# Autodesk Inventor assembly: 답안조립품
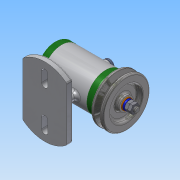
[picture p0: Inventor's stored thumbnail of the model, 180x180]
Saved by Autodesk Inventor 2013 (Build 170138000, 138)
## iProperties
Created: 2017-12
Part Number: 답안조립품
Document SubType Name: Assembly
Designer: Administrator
Author: Administrator
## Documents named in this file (14)
- C:\Users\Administrator\Desktop\471208V1024\답안조립품.iam
- C:\Users\Administrator\Desktop\471208V1024\V벨트풀리.ipt
- C:\Users\Administrator\Desktop\471208V1024\고무캡.ipt
- C:\Users\Administrator\Desktop\471208V1024\너트 M 8.ipt
- C:\Users\Administrator\Desktop\471208V1024\뒤커버.ipt
- C:\Users\Administrator\Desktop\471208V1024\베어링 15 x 32 x 9.ipt
- C:\Users\Administrator\Desktop\471208V1024\본체.ipt
- C:\Users\Administrator\Desktop\471208V1024\볼트 M4 x 12.ipt
- C:\Users\Administrator\Desktop\471208V1024\스프링와셔 8.ipt
- C:\Users\Administrator\Desktop\471208V1024\앞커버.ipt
- C:\Users\Administrator\Desktop\471208V1024\오일 실 15 25 7.ipt
- C:\Users\Administrator\Desktop\471208V1024\와셔 8x17.ipt
- C:\Users\Administrator\Desktop\471208V1024\축.ipt
- C:\Users\Administrator\Desktop\471208V1024\키 3 x 3 x 12.ipt
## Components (2 placed, 2 different names)
1. V벨트풀리:1
2. 고무캡:1
